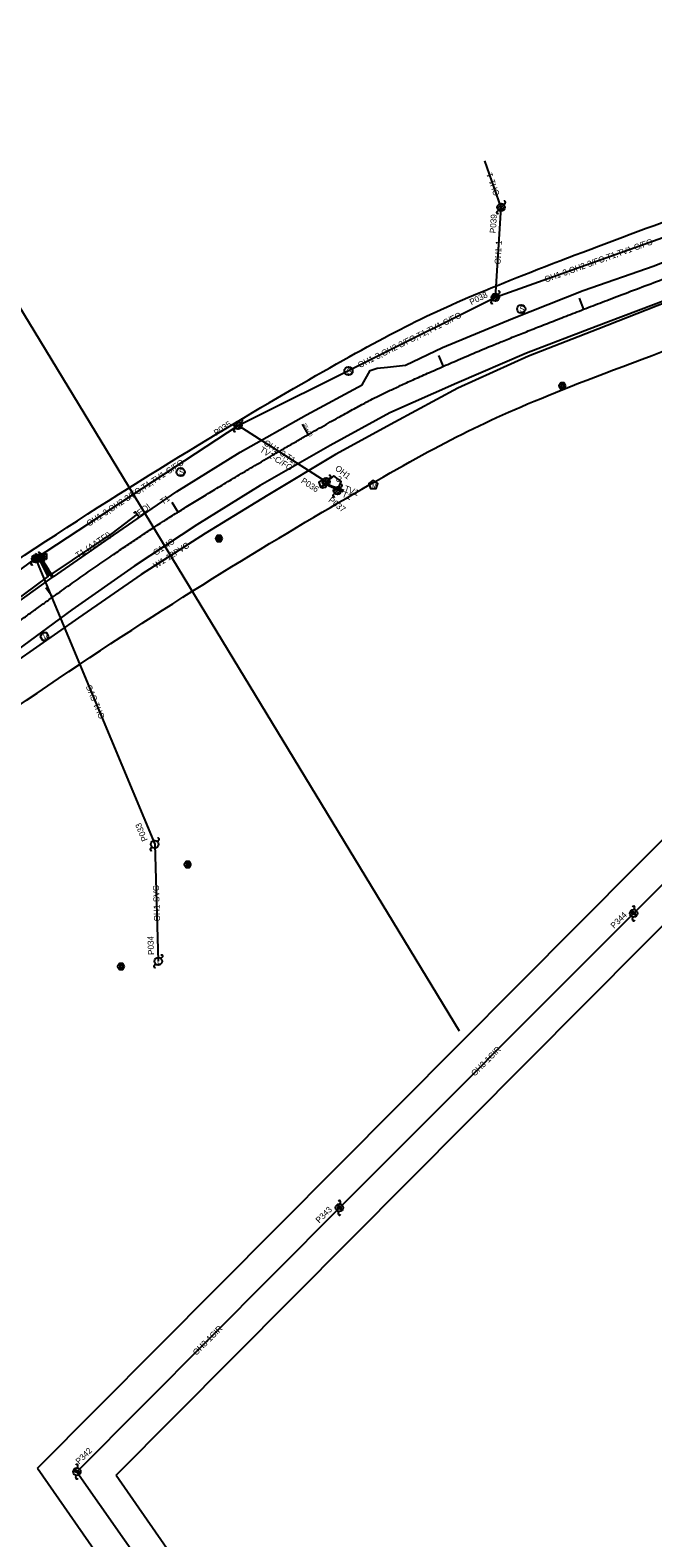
# Model space of a CAD drawing. Extents: x 1991878 to 2008544, y 770238 to 1141211.
# Drawn here: x 2005776 to 2006187, y 1139564 to 1140559 of the extents above; entities that cross this region are included whole.
import ezdxf

# ---------------------------------------------------------------- set-up
doc = ezdxf.new("R2010")
doc.units = 0
for name, color, linetype in [('RD_EX_SU_Gas', 7, 'Continuous'), ('RD_EX_SU_H2O', 7, 'Continuous'), ('RD_EX_SU_Ovhd', 7, 'Continuous'), ('RD_EX_SU_Pole', 7, 'Continuous'), ('RD_EX_SU_Sewer', 7, 'Continuous'), ('RD_EX_SU_SwpLmt', 7, 'Continuous'), ('RD_EX_SU_Telecom', 7, 'Continuous'), ('RD_EX_SU_TX_Gas', 7, 'Continuous'), ('RD_EX_SU_TX_H2O', 7, 'Continuous'), ('RD_EX_SU_TX_Ovhd', 7, 'Continuous'), ('RD_EX_SU_TX_Pole', 7, 'Continuous'), ('RD_EX_SU_TX_Telecom', 7, 'Continuous'), ('RD_HC_Cl', 7, 'Continuous')]:
    doc.layers.add(name, color=color, linetype=linetype)

msp = doc.modelspace()

# ---------------------------------------------------------------- linework, layer by layer
at = {"layer": 'RD_EX_SU_Gas'}
msp.add_lwpolyline([(2006659, 1140580.57), (2006616.24, 1140554.03), (2006572.17, 1140528.34), (2006527.84, 1140504.87), (2006480.11, 1140482.2), (2006433.28, 1140463.04), (2006387.65, 1140445.69), (2006335.52, 1140428.39), (2006290.66, 1140413.7), (2006243.38, 1140398.08), (2006195.4, 1140380.79), (2006149.48, 1140363.23), (2006103.48, 1140345.61), (2006057.3, 1140326.02), (2006013.07, 1140306.27), (2005973.69, 1140284.77), (2005927.56, 1140258.36), (2005885.79, 1140232.42), (2005844.4, 1140205.05), (2005803.2, 1140176.39), (2005763.13, 1140146.95)], dxfattribs=at)
at = {"layer": 'RD_EX_SU_H2O'}
msp.add_lwpolyline([(2006662.73, 1140571.78), (2006621.15, 1140545.52), (2006575.62, 1140521.49), (2006523.9, 1140492.67), (2006480.95, 1140479.12), (2006464.19, 1140470.57), (2006435.9, 1140460.17), (2006387.84, 1140444.29), (2006337.78, 1140427.16), (2006284, 1140408), (2006245, 1140396.17), (2006195.82, 1140379.38), (2006150.58, 1140361.49), (2006104.78, 1140343.73), (2006057.98, 1140322.59), (2006016.46, 1140300.24), (2005977.38, 1140278.75), (2005932.66, 1140252.06), (2005891.14, 1140226.62), (2005848.84, 1140199.57), (2005807.57, 1140171.15), (2005766.02, 1140142.13)], dxfattribs=at)
for points in [[(2006002.24, 1140261.82), (2005999.34, 1140259.71), (2006000.45, 1140256.3), (2006004.03, 1140256.3), (2006005.14, 1140259.71)], [(2005788.06, 1140158.72), (2005786.62, 1140161.22), (2005783.73, 1140161.22), (2005782.29, 1140158.72), (2005783.73, 1140156.22), (2005786.62, 1140156.22)]]:
    msp.add_lwpolyline(points, close=True, dxfattribs=at)
at = {"layer": 'RD_EX_SU_Ovhd'}
for p, q in [((2006086.59, 1140441.91), (2006075.85, 1140472.55)), ((2006082.85, 1140382.57), (2006086.59, 1140441.91)), ((2006082.85, 1140382.57), (2006221.67, 1140432.07)), ((2005912.95, 1140298.05), (2006082.85, 1140382.57)), ((2005779.22, 1140210.16), (2005912.95, 1140298.05)), ((2005971.09, 1140260.88), (2005912.95, 1140298.05)), ((2005637.78, 1140106.93), (2005779.22, 1140210.16)), ((2005779.22, 1140210.16), (2005857.86, 1140021.64)), ((2006371.59, 1140174.52), (2006174.14, 1139975.99)), ((2005857.86, 1140021.64), (2005860.27, 1139944.47)), ((2006174.14, 1139975.99), (2005979.86, 1139781.75)), ((2005979.86, 1139781.75), (2005806.49, 1139607.62)), ((2005806.49, 1139607.62), (2005944.1, 1139411.01))]:
    msp.add_line(p, q, dxfattribs=at)
msp.add_lwpolyline([(2005978.55, 1140254.99), (2005981.09, 1140260.92), (2005976.27, 1140264.72), (2005971.09, 1140260.88)], dxfattribs=at)
at = {"layer": 'RD_EX_SU_Pole'}
for p, q in [((2006083.76, 1140439.08), (2006084.82, 1140440.14)), ((2006084.17, 1140441.26), (2006087.23, 1140444.32)), ((2006084.82, 1140440.14), (2006088.36, 1140443.68)), ((2006085.94, 1140439.49), (2006089, 1140442.56)), ((2006088.36, 1140443.68), (2006089.42, 1140444.74)), ((2006080.02, 1140379.74), (2006081.08, 1140380.8)), ((2006080.43, 1140381.92), (2006083.49, 1140384.98)), ((2006081.08, 1140380.8), (2006084.61, 1140384.34)), ((2006082.2, 1140380.16), (2006085.26, 1140383.22)), ((2006084.61, 1140384.34), (2006085.67, 1140385.4)), ((2005910.12, 1140295.22), (2005911.18, 1140296.28)), ((2005910.53, 1140297.4), (2005913.59, 1140300.46)), ((2005911.18, 1140296.28), (2005914.71, 1140299.82)), ((2005912.3, 1140295.64), (2005915.36, 1140298.7)), ((2005914.71, 1140299.82), (2005915.77, 1140300.88)), ((2005968.26, 1140258.05), (2005969.32, 1140259.11)), ((2005968.67, 1140260.23), (2005971.73, 1140263.29)), ((2005969.32, 1140259.11), (2005972.85, 1140262.65)), ((2005970.44, 1140258.46), (2005973.5, 1140261.52)), ((2005972.85, 1140262.65), (2005973.91, 1140263.71)), ((2005976.14, 1140254.34), (2005979.2, 1140257.4)), ((2005976.78, 1140253.22), (2005980.32, 1140256.75)), ((2005980.32, 1140256.75), (2005981.38, 1140257.81)), ((2005975.72, 1140252.16), (2005976.78, 1140253.22)), ((2005977.91, 1140252.57), (2005980.97, 1140255.63)), ((2005776.39, 1140207.34), (2005777.45, 1140208.4)), ((2005776.8, 1140209.52), (2005779.86, 1140212.58)), ((2005777.45, 1140208.4), (2005780.98, 1140211.93)), ((2005778.57, 1140207.75), (2005781.63, 1140210.81)), ((2005780.98, 1140211.93), (2005782.04, 1140212.99)), ((2005855.03, 1140018.81), (2005856.09, 1140019.87)), ((2005859.63, 1140023.4), (2005860.69, 1140024.46)), ((2006174.59, 1139978.45), (2006174.86, 1139979.93)), ((2006173.42, 1139972.06), (2006173.69, 1139973.53)), ((2005857.44, 1139941.64), (2005858.5, 1139942.7)), ((2005862.03, 1139946.24), (2005863.09, 1139947.3)), ((2005979.14, 1139777.82), (2005979.41, 1139779.29)), ((2005980.3, 1139784.21), (2005980.57, 1139785.69)), ((2005806.93, 1139610.08), (2005807.2, 1139611.56)), ((2005805.77, 1139603.69), (2005806.04, 1139605.16))]:
    msp.add_line(p, q, dxfattribs=at)
for points in [[(2006172.67, 1139977.42), (2006174.5, 1139976.23), (2006172.84, 1139976.07), (2006175.91, 1139974.93), (2006175.91, 1139974.93), (2006173.73, 1139975.97), (2006175.32, 1139976.1)], [(2005978.39, 1139783.18), (2005980.22, 1139781.99), (2005978.56, 1139781.83), (2005981.63, 1139780.69), (2005981.63, 1139780.69), (2005979.45, 1139781.73), (2005981.04, 1139781.86)], [(2005805.02, 1139609.05), (2005806.84, 1139607.87), (2005805.19, 1139607.7), (2005808.26, 1139606.56), (2005808.26, 1139606.56), (2005806.08, 1139607.6), (2005807.67, 1139607.73)]]:
    msp.add_lwpolyline(points, close=True, dxfattribs=at)
for centre in [(2006086.59, 1140441.91), (2006082.85, 1140382.57), (2005912.95, 1140298.05), (2005971.09, 1140260.88), (2005978.55, 1140254.99), (2005779.22, 1140210.16), (2005857.86, 1140021.64), (2006174.14, 1139975.99), (2005860.27, 1139944.47), (2005979.86, 1139781.75), (2005806.49, 1139607.62)]:
    msp.add_circle(centre, 2.5, dxfattribs=at)
for centre, start, end in [((2006088.89, 1140445.27), 315.01158, 135.01158), ((2006084.29, 1140438.55), 135.01158, 315.01158), ((2006085.14, 1140385.93), 315.01158, 135.01158), ((2006080.55, 1140379.21), 135.01158, 315.01158), ((2005915.24, 1140301.41), 315.01158, 135.01158), ((2005910.65, 1140294.69), 135.01158, 315.01158), ((2005968.79, 1140257.52), 135.01158, 315.01158), ((2005973.38, 1140264.24), 315.01158, 135.01158), ((2005980.85, 1140258.34), 315.01158, 135.01158), ((2005976.25, 1140251.63), 135.01158, 315.01158), ((2005776.92, 1140206.8), 135.01158, 315.01158), ((2005781.51, 1140213.52), 315.01158, 135.01158), ((2005855.56, 1140018.28), 135.01158, 315.01158), ((2005860.16, 1140024.99), 315.01158, 135.01158), ((2006174.12, 1139980.06), 349.68899, 169.68899), ((2006174.16, 1139971.92), 169.68899, 349.68899), ((2005862.56, 1139947.83), 315.01158, 135.01158), ((2005857.97, 1139941.11), 135.01158, 315.01158), ((2005979.84, 1139785.82), 349.68899, 169.68899), ((2005979.88, 1139777.68), 169.68899, 349.68899), ((2005806.46, 1139611.69), 349.68899, 169.68899), ((2005806.51, 1139603.55), 169.68899, 349.68899)]:
    msp.add_arc(centre, 0.75, start, end, dxfattribs=at)
at = {"layer": 'RD_EX_SU_Sewer'}
for points in [[(2006129.44, 1140324.06), (2006128.28, 1140326.06), (2006125.98, 1140326.06), (2006124.82, 1140324.06), (2006125.98, 1140322.06), (2006128.28, 1140322.06)], [(2006127.95, 1140324.87), (2006126.31, 1140324.87), (2006126.31, 1140323.24), (2006127.95, 1140323.24)], [(2005902.67, 1140223.47), (2005901.51, 1140225.47), (2005899.21, 1140225.47), (2005898.05, 1140223.47), (2005899.21, 1140221.47), (2005901.51, 1140221.47)], [(2005901.18, 1140224.29), (2005899.54, 1140224.29), (2005899.54, 1140222.65), (2005901.17, 1140222.65)], [(2005882.02, 1140008.24), (2005880.87, 1140010.24), (2005878.56, 1140010.24), (2005877.41, 1140008.24), (2005878.56, 1140006.24), (2005880.87, 1140006.24)], [(2005880.53, 1140009.06), (2005878.9, 1140009.06), (2005878.9, 1140007.43), (2005880.53, 1140007.43)], [(2005838.04, 1139941.08), (2005836.88, 1139943.07), (2005834.58, 1139943.07), (2005833.42, 1139941.08), (2005834.58, 1139939.08), (2005836.88, 1139939.08)], [(2005836.55, 1139941.89), (2005834.91, 1139941.89), (2005834.91, 1139940.26), (2005836.54, 1139940.26)]]:
    msp.add_lwpolyline(points, close=True, dxfattribs=at)
for centre in [(2006099.91, 1140374.88), (2005985.86, 1140333.86), (2005875.06, 1140267.25)]:
    msp.add_circle(centre, 2.75, dxfattribs=at)
at = {"layer": 'RD_EX_SU_SwpLmt'}
for p, q in [((2005780.53, 1139609.9), (2006044.93, 1139230.29)), ((2005832.44, 1139605.35), (2006593.4, 1138512.84))]:
    msp.add_line(p, q, dxfattribs=at)
for points in [[(2005780.53, 1139609.9), (2006733.27, 1140567.21), (2006823.57, 1140659.06)], [(2005832.44, 1139605.35), (2006761.62, 1140538.99), (2006847.85, 1140632.58)]]:
    msp.add_lwpolyline(points, dxfattribs=at)
for points in [[(2005347.6, 1139821.95), (2005413.49, 1139866.73), (2005588.16, 1139984.08), (2005817.83, 1140151.69), (2006031.43, 1140278.81), (2006110.28, 1140318.03), (2006387.29, 1140416.7), (2006495.91, 1140463.06), (2006601.39, 1140518.44), (2006718.46, 1140585.62), (2006783.57, 1140627.26), (2006823.57, 1140659.06)], [(2005347.6, 1139821.95), (2005413.49, 1139866.73), (2005588.16, 1139984.08), (2005817.83, 1140151.69), (2006031.43, 1140278.81), (2006110.28, 1140318.03), (2006387.29, 1140416.7), (2006495.91, 1140463.06), (2006601.39, 1140518.44), (2006706.19, 1140578.58), (2006762.55, 1140613.92), (2006787.85, 1140632.08)], [(2005307.04, 1139891.13), (2005371.11, 1139934.66), (2005544.09, 1140050.96), (2005773.7, 1140218.52), (2005993.11, 1140349.1), (2006068.08, 1140386.39), (2006199.13, 1140434.31), (2006247.03, 1140451.84)]]:
    msp.add_open_spline(points, degree=3, dxfattribs=at)
at = {"layer": 'RD_EX_SU_Telecom'}
for p, q in [((2005777.58, 1140212.31), (2005779.99, 1140211.11)), ((2005777.58, 1140212.31), (2005777.58, 1140208.56)), ((2005777.58, 1140208.56), (2005779.99, 1140209.77)), ((2005779.09, 1140213.46), (2005781.49, 1140212.26)), ((2005779.09, 1140213.46), (2005779.09, 1140209.71)), ((2005779.09, 1140209.71), (2005781.49, 1140210.92)), ((2005782.67, 1140211.11), (2005785.08, 1140212.31)), ((2005782.67, 1140209.77), (2005785.08, 1140208.56)), ((2005784.18, 1140212.26), (2005786.59, 1140213.46)), ((2005784.18, 1140210.92), (2005786.59, 1140209.71)), ((2005785.08, 1140208.56), (2005785.08, 1140212.31)), ((2005786.59, 1140209.71), (2005786.59, 1140213.46))]:
    msp.add_line(p, q, dxfattribs=at)
for points in [[(2005782.4, 1140210.68), (2005783.36, 1140209.78), (2005787.76, 1140202.94), (2005791.09, 1140198.01), (2005830.75, 1140225.72), (2005872.56, 1140254.44), (2005914.21, 1140280.3), (2005958.19, 1140305.05), (2005994.94, 1140324.79), (2006000.07, 1140334.17), (2006004.81, 1140335.92), (2006011.67, 1140336.58), (2006023.53, 1140337.8), (2006047.93, 1140349.44), (2006094.26, 1140368.64), (2006140.88, 1140386.98), (2006187.64, 1140403.41), (2006220.74, 1140416.68), (2006225.13, 1140419), (2006224.39, 1140424.64), (2006222.64, 1140429.44), (2006222.32, 1140430.74)], [(2005982.36, 1140254.28), (2005975.13, 1140256.99), (2005969.77, 1140259.54), (2005969.2, 1140259.66)], [(2005982.68, 1140255.12), (2005975.4, 1140257.77), (2005970.93, 1140259.52), (2005971.09, 1140260.88)], [(2005782.4, 1140210.68), (2005782.62, 1140209.14), (2005786.35, 1140201.83), (2005788.24, 1140199.11), (2005790.07, 1140200.2), (2005829.9, 1140226.64), (2005846.51, 1140239.39)], [(2005506.12, 1140009.88), (2005507.47, 1140009.02), (2005512.22, 1140003.56), (2005515.62, 1139999), (2005546.74, 1140021.71), (2005586.88, 1140050.43), (2005626.74, 1140079.61), (2005667.94, 1140108.45), (2005708.03, 1140137.8), (2005748.45, 1140167.76), (2005790.26, 1140197.61), (2005787.32, 1140202.47), (2005783.02, 1140209.42), (2005782.4, 1140210.68)], [(2005666.81, 1140109.05), (2005706.93, 1140138.78), (2005747.83, 1140169.15), (2005787.63, 1140198.28), (2005785.98, 1140201.22), (2005782.12, 1140209.04), (2005782.4, 1140210.68)]]:
    msp.add_lwpolyline(points, dxfattribs=at)
for points in [[(2005969.2, 1140262.66), (2005966.35, 1140260.59), (2005967.44, 1140257.23), (2005970.97, 1140257.23), (2005972.06, 1140260.59)], [(2005782.4, 1140213.68), (2005779.55, 1140211.61), (2005780.64, 1140208.25), (2005784.16, 1140208.25), (2005785.25, 1140211.61)]]:
    msp.add_lwpolyline(points, close=True, dxfattribs=at)
for centre in [(2005781.33, 1140210.44), (2005782.84, 1140211.59)]:
    msp.add_circle(centre, 1.5, dxfattribs=at)
at = {"layer": 'RD_EX_SU_TX_Telecom'}
msp.add_lwpolyline([(2005844.1, 1140240.06), (2005845.29, 1140240.98), (2005847.73, 1140237.81), (2005846.54, 1140236.89)], dxfattribs=at)
at = {"layer": 'RD_HC_Cl'}
for p, q in [((2005680.38, 1140521.08), (2006058.95, 1139898.61)), ((2006138.25, 1140381.92), (2006141.14, 1140374.46)), ((2006045.28, 1140344.23), (2006048.47, 1140336.89)), ((2005955.3, 1140298.78), (2005959.27, 1140291.84)), ((2005869.13, 1140247.4), (2005873.38, 1140240.63)), ((2005785.9, 1140191.15), (2005790.55, 1140184.64))]:
    msp.add_line(p, q, dxfattribs=at)
msp.add_open_spline([(2005275.25, 1139802.58), (2005417.33, 1139911.24), (2005548.93, 1140008.55), (2005664.1, 1140090.03), (2005747, 1140153.49), (2005819.82, 1140205.85), (2005880.88, 1140246.35), (2005986.62, 1140308.11), (2006024.68, 1140326.82), (2006100.51, 1140359.48), (2006273.91, 1140424.96), (2006364.15, 1140455.15), (2006461.52, 1140489.97), (2006524.81, 1140519.99), (2006584.45, 1140553.16), (2006699.96, 1140622.09), (2006754.11, 1140664.4), (2006830.67, 1140723.8), (2007317.85, 1141134.95)], degree=2, dxfattribs=at)

# ---------------------------------------------------------------- texts
at = {"layer": 'RD_EX_SU_H2O'}
for s, p in [('M', (2006000.87, 1140256.78)), ('V', (2005783.96, 1140156.84))]:
    msp.add_text(s, height=3.75, dxfattribs=at).set_placement(p)
at = {"layer": 'RD_EX_SU_Pole'}
for p in [(2005857.05, 1140019.7), (2005859.45, 1139942.54)]:
    msp.add_text('L', height=4, rotation=0.01158, dxfattribs=at).set_placement(p)
at = {"layer": 'RD_EX_SU_Sewer'}
for p in [(2006098.71, 1140372.92), (2005984.66, 1140331.9), (2005873.86, 1140265.28)]:
    msp.add_text('S', height=3.93, dxfattribs=at).set_placement(p)
at = {"layer": 'RD_EX_SU_Telecom'}
for p in [(2005967.98, 1140257.43), (2005781.17, 1140208.45)]:
    msp.add_text('T', height=3.75, dxfattribs=at).set_placement(p)
at = {"layer": 'RD_EX_SU_TX_Gas'}
msp.add_text('G1-4S', height=4, rotation=33.473, dxfattribs=at).set_placement((2005858.48, 1140211.93))
at = {"layer": 'RD_EX_SU_TX_H2O'}
msp.add_text('W1-12PVC', height=4, rotation=32.59791, dxfattribs=at).set_placement((2005858.6, 1140203.42))
at = {"layer": 'RD_EX_SU_TX_Ovhd'}
for s, rotation, p in [('OH1-1', 109.31305, (2006085.73, 1140450.4)), ('OH1-1', 86.39253, (2006086.21, 1140404.2)), ('OH1-3,OH2-3/FO,T1,TV1-C/FO', 19.62616, (2006116.11, 1140392.31)), ('OH1-3,OH2-3/FO,T1,TV1-C/FO', 26.44893, (2005993.31, 1140335.8)), ('OH1-3,T1,', 327.40635, (2005929.47, 1140285.47)), ('TV1-C/FO', 327.40635, (2005926.88, 1140280.95)), ('OH1-3,OH2-3/FO,T1,TV1-C/FO', 33.31251, (2005814.51, 1140231.16)), ('OH1', 321.71656, (2005976.61, 1140269.01)), ('-3', 321.71656, (2005975.74, 1140263.06)), ('OH1-SVC', 112.64245, (2005825.1, 1140105.36)), ('OH1-SVC', 91.78669, (2005861.44, 1139970.86)), ('OH3-1CIR', 44.99347, (2006069.2, 1139868.24)), ('OH3-1CIR', 45.12497, (2005885.39, 1139684.04))]:
    msp.add_text(s, height=4, rotation=rotation, dxfattribs=at).set_placement(p)
at = {"layer": 'RD_EX_SU_TX_Pole'}
for s, rotation, p in [('P039', 86.39253, (2006083.09, 1140424.78)), ('P038', 26.44893, (2006067.03, 1140377.32)), ('P035', 33.31251, (2005898.52, 1140291.03)), ('P036', 327.40635, (2005954.09, 1140260.42)), ('P037', 321.71656, (2005972.18, 1140248.08)), ('P033', 112.64245, (2005853.4, 1140024.56)), ('P344', 44.99347, (2006161.26, 1139965.79)), ('P034', 91.78669, (2005857.46, 1139948.68)), ('P343', 45.12497, (2005966.53, 1139771.36)), ('P342', 45.12497, (2005808.05, 1139612.26))]:
    msp.add_text(s, height=4, rotation=rotation, dxfattribs=at).set_placement(p)
at = {"layer": 'RD_EX_SU_TX_Telecom'}
for s, rotation, p in [('TV1', 340.02571, (2005982.64, 1140254.79)), ('EOI', 37.5317, (2005848.13, 1140238.12)), ('T1', 34.48715, (2005863.17, 1140245.53)), ('T1', 339.47873, (2005981.22, 1140250.98)), ('T1-(AATFI)', 33.57523, (2005807.2, 1140210.2))]:
    msp.add_text(s, height=4, rotation=rotation, dxfattribs=at).set_placement(p)
at = {"layer": 'RD_HC_Cl'}
msp.add_text('35+00', height=2.5, rotation=299.81038, dxfattribs=at).set_placement((2005955.33, 1140298.72))

doc.saveas('drawing.dxf')
